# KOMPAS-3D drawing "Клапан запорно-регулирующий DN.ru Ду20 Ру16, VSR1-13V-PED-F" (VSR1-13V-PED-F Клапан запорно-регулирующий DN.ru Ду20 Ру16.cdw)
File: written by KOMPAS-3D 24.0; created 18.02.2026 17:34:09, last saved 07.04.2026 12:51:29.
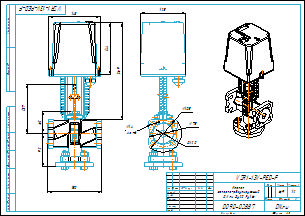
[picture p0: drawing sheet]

Document properties: Автор: R2D2; Форматы листов документа: A3; Полное имя файла: VSR1-13V-PED-F Клапан запорно-регулирующий DN.ru Ду20 Ру16.m3d; Масса: 6.9; Наименование: Клапан запорно-регулирующий DN.ru Ду20 Ру16; Количество листов документа: 1; Примечание: D090-02887

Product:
- Body: Тело 2  | qty 1
    Масса: 21.746757
- Part/product: Клапан запорно-регулирующий DN.ru Ду20 Ру16  | designation VSR1-13V-PED-F
    Масса: 6.9
    Раздел спецификации: Прочие изделия
    Примечание: D090-02887

Views: Вид 1, Спереди
Referenced files in E:\Работа\Зайцев\Солянка\VSR1-13V-PED-F Клапан запорно-регулирующий DN.ru\DN15\DN15 Kv0.16\: VSR1-13V-PED-F Клапан запорно-регулирующий DN.ru Ду15 Ру16.m3d
Referenced files in E:\Работа\Зайцев\Солянка\VSR1-13V-PED-F Клапан запорно-регулирующий DN.ru\DN20\: VSR1-13V-PED-F Клапан запорно-регулирующий DN.ru Ду20 Ру16.m3d
Referenced files in E:\Работа\Зайцев\Для компаса\: чертеж DN.ru А3.cdt
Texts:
  Линейный размер
  VSR1-13V-PED-F
  чертеж DN.ru А3.cdt
  Клапан
  запорно-регулирующий
  DN.ru Ду20 Ру16
  Клапан запорно-регулирующий DN.ru Ду20 Ру16
  VSR1-13V-PED-F Клапан запорно-регулирующий DN.ru Ду20 Ру16
Dimensions and other numbers on the sheet: 0; 3; 2; 4; 150; 143; 62; 137; 92; 269; 144; 1:2; 1; 6,9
